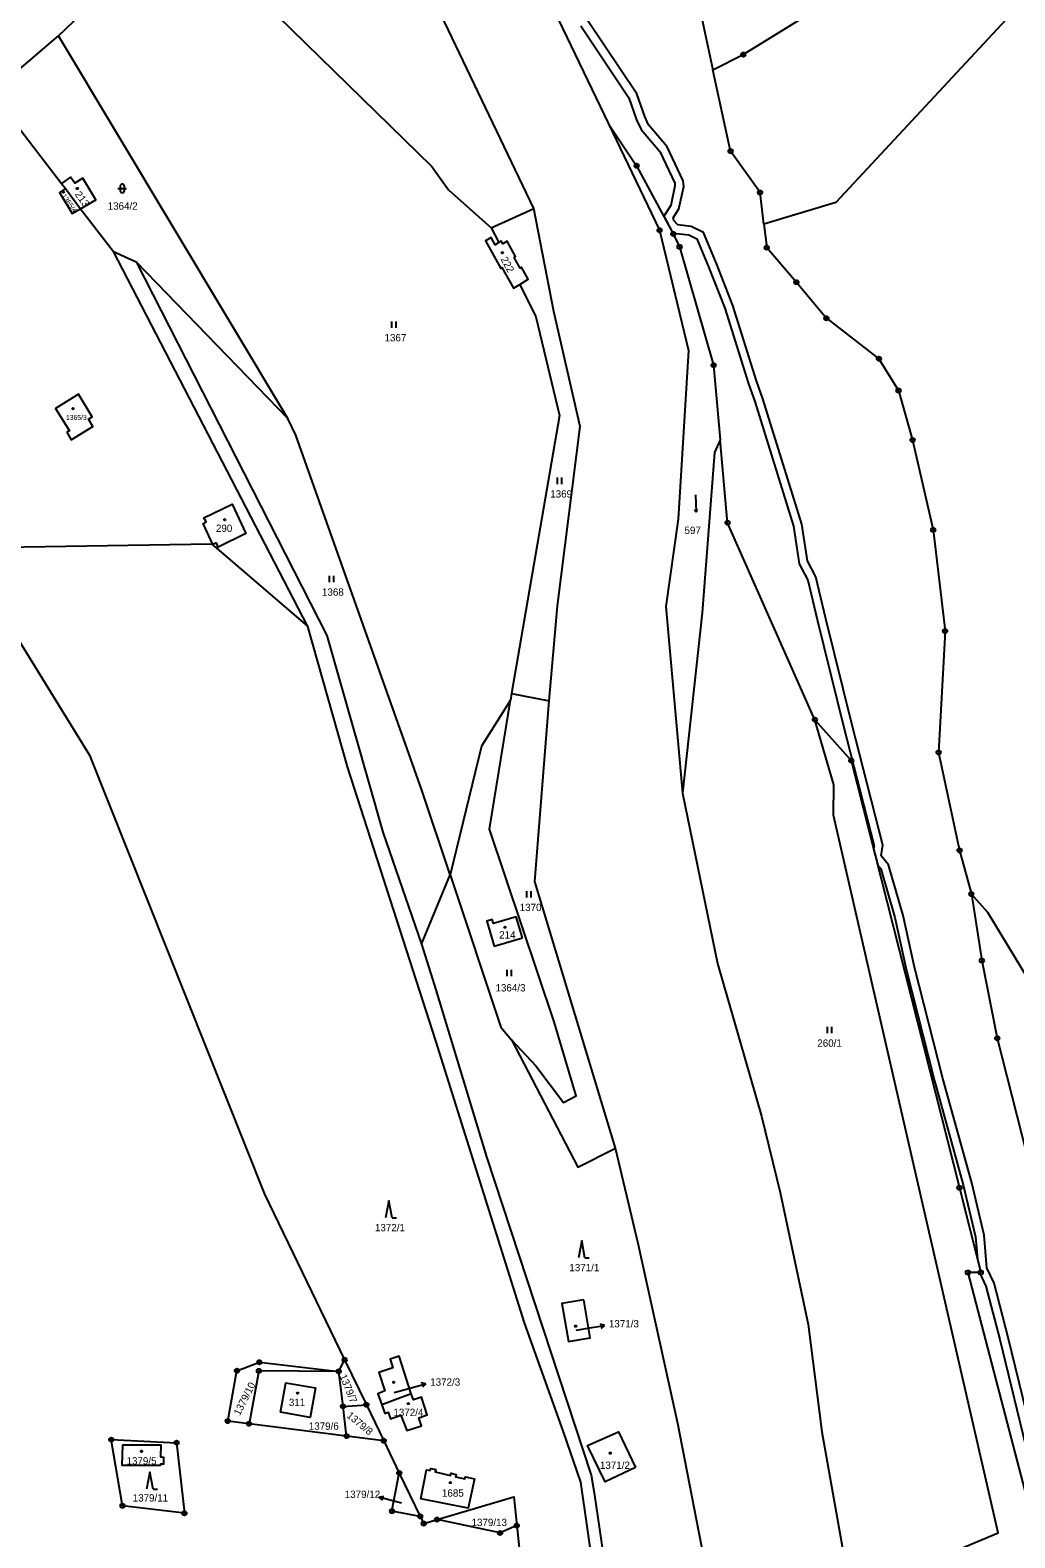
# Model space of a CAD drawing. Extents: x -680203 to -673936, y -1102717 to -1093650.
# Drawn here: x -675574.5 to -675346.1, y -1100750.7 to -1100400.9 of the extents above; entities that cross this region are included whole.
import ezdxf

# ---------------------------------------------------------------- set-up
doc = ezdxf.new("R2010")
doc.units = 0
for name, color, linetype in [('_Ideová část', 7, 'Continuous'), ('SOxx02xx_Koleje_param další_Popis10', 7, 'Continuous'), ('SOxx02xx_Staničení_Popis10', 7, 'Continuous'), ('SOxxxxxx_Koleje_hlavní_body_Popis10', 7, 'Continuous'), ('SOxxxxxx_Koleje_LN_parametry_Popis10', 7, 'Continuous'), ('SOxxxxxx_Koleje_param další_Popis10', 7, 'Continuous'), ('SOxxxxxx_Osa_bod_P', 7, 'Continuous'), ('x_prac', 7, 'Continuous')]:
    doc.layers.add(name, color=color, linetype=linetype)

msp = doc.modelspace()

# ---------------------------------------------------------------- linework, layer by layer
at = {"layer": '_Ideová část'}
msp.add_circle((-676417.7, -1099401.52), 1287.12, dxfattribs=at)
at = {"layer": 'SOxx02xx_Koleje_param další_Popis10'}
for centre, radius in [((-675409.1, -1100406.53), 0.5), ((-675409.1, -1100406.53), 0.0303), ((-675412.03, -1100428.94), 0.5), ((-675412.03, -1100428.94), 0.0303), ((-675433.83, -1100432.32), 0.5), ((-675433.83, -1100432.32), 0.0303), ((-675405.2, -1100438.53), 0.5), ((-675405.2, -1100438.53), 0.0303), ((-675428.52, -1100447.29), 0.5), ((-675428.52, -1100447.29), 0.5), ((-675428.52, -1100447.29), 0.0303), ((-675428.52, -1100447.29), 0.0303), ((-675425.33, -1100448.15), 0.5), ((-675425.33, -1100448.15), 0.0303), ((-675423.89, -1100451.14), 0.5), ((-675423.89, -1100451.14), 0.0303), ((-675403.66, -1100451.31), 0.5), ((-675403.66, -1100451.31), 0.0303), ((-675396.78, -1100459.34), 0.5), ((-675396.78, -1100459.34), 0.0303), ((-675389.82, -1100467.72), 0.5), ((-675389.82, -1100467.72), 0.0303), ((-675415.99, -1100478.63), 0.5), ((-675415.99, -1100478.63), 0.0303), ((-675377.65, -1100477.12), 0.5), ((-675377.65, -1100477.12), 0.0303), ((-675373.09, -1100484.48), 0.5), ((-675373.09, -1100484.48), 0.0303), ((-675369.84, -1100495.99), 0.5), ((-675369.84, -1100495.99), 0.0303), ((-675412.75, -1100515.16), 0.5), ((-675412.75, -1100515.16), 0.0303), ((-675365.05, -1100516.82), 0.5), ((-675365.05, -1100516.82), 0.0303), ((-675362.3, -1100540.29), 0.5), ((-675362.3, -1100540.29), 0.0303), ((-675392.49, -1100560.86), 0.5), ((-675392.49, -1100560.86), 0.0303), ((-675384.05, -1100570.35), 0.5), ((-675384.05, -1100570.35), 0.0303), ((-675363.8, -1100568.47), 0.5), ((-675363.8, -1100568.47), 0.0303), ((-675358.93, -1100591.19), 0.5), ((-675358.93, -1100591.19), 0.0303), ((-675356.2, -1100601.34), 0.5), ((-675356.2, -1100601.34), 0.0303), ((-675353.76, -1100616.75), 0.5), ((-675353.76, -1100616.75), 0.0303), ((-675350.19, -1100634.79), 0.5), ((-675350.19, -1100634.79), 0.0303), ((-675358.95, -1100669.47), 0.5), ((-675358.95, -1100669.47), 0.0303), ((-675357.01, -1100689.14), 0.5), ((-675357.01, -1100689.14), 0.0303), ((-675354, -1100689.14), 0.5), ((-675354, -1100689.14), 0.0303), ((-675521.35, -1100709.97), 0.5), ((-675521.35, -1100709.97), 0.0303), ((-675501.56, -1100709.41), 0.5), ((-675501.56, -1100709.41), 0.0303), ((-675526.54, -1100711.93), 0.5), ((-675526.54, -1100711.93), 0.0303), ((-675521.47, -1100711.97), 0.5), ((-675521.47, -1100711.97), 0.0303), ((-675502.94, -1100712.08), 0.5), ((-675502.94, -1100712.08), 0.0303), ((-675501.93, -1100720.2), 0.5), ((-675501.93, -1100720.2), 0.0303), ((-675496.53, -1100719.83), 0.5), ((-675496.53, -1100719.83), 0.0303), ((-675528.69, -1100723.61), 0.5), ((-675528.69, -1100723.61), 0.0303), ((-675523.73, -1100724.24), 0.5), ((-675523.73, -1100724.24), 0.0303), ((-675555.69, -1100727.93), 0.5), ((-675501.1, -1100727.11), 0.5), ((-675501.1, -1100727.11), 0.0303), ((-675492.5, -1100728.18), 0.5), ((-675555.69, -1100727.93), 0.0303), ((-675540.56, -1100728.63), 0.5), ((-675540.56, -1100728.63), 0.0303), ((-675492.5, -1100728.18), 0.0303), ((-675488.89, -1100735.67), 0.5), ((-675488.89, -1100735.67), 0.0303), ((-675553.09, -1100743.26), 0.5), ((-675553.09, -1100743.26), 0.0303), ((-675538.72, -1100745.02), 0.5), ((-675538.72, -1100745.02), 0.0303), ((-675490.58, -1100744.52), 0.5), ((-675490.58, -1100744.52), 0.0303), ((-675484.03, -1100745.74), 0.5), ((-675484.03, -1100745.74), 0.0303), ((-675483.23, -1100747.39), 0.5), ((-675483.23, -1100747.39), 0.0303), ((-675480.13, -1100746.47), 0.5), ((-675480.13, -1100746.47), 0.0303), ((-675461.64, -1100747.86), 0.5), ((-675461.64, -1100747.86), 0.0303), ((-675465.51, -1100749.59), 0.5), ((-675465.51, -1100749.59), 0.0303)]:
    msp.add_circle(centre, radius, dxfattribs=at)
at = {"layer": 'SOxx02xx_Staničení_Popis10'}
for p, q in [((-675447.83, -1100702.49), (-675444.22, -1100701.92)), ((-675444.22, -1100701.92), (-675441.26, -1100701.45)), ((-675441.26, -1100701.45), (-675442.32, -1100701.11)), ((-675441.26, -1100701.45), (-675442.17, -1100702.1)), ((-675490.1, -1100717), (-675485.6, -1100715.77)), ((-675485.6, -1100715.77), (-675482.7, -1100714.99)), ((-675482.7, -1100714.99), (-675483.8, -1100714.77)), ((-675482.7, -1100714.99), (-675483.54, -1100715.74)), ((-675493.61, -1100741.24), (-675492.51, -1100741.02)), ((-675490.71, -1100742.02), (-675493.61, -1100741.24)), ((-675493.61, -1100741.24), (-675492.77, -1100741.99)), ((-675488.37, -1100742.66), (-675490.71, -1100742.02))]:
    msp.add_line(p, q, dxfattribs=at)
at = {"layer": 'SOxxxxxx_Koleje_hlavní_body_Popis10'}
for p, q in [((-675553.66, -1100437.07), (-675553.66, -1100438.07)), ((-675552.66, -1100438.07), (-675552.66, -1100437.07)), ((-675554.16, -1100437.57), (-675552.16, -1100437.57)), ((-675490.65, -1100469.96), (-675490.65, -1100468.46)), ((-675489.65, -1100469.96), (-675489.65, -1100468.46)), ((-675452.18, -1100506.2), (-675452.18, -1100504.7)), ((-675451.18, -1100506.2), (-675451.18, -1100504.7)), ((-675420.15, -1100508.71), (-675420.01, -1100512.73)), ((-675420.01, -1100512.73), (-675420.36, -1100512.09)), ((-675420.01, -1100512.73), (-675419.69, -1100512.06)), ((-675505.1, -1100528.98), (-675505.1, -1100527.48)), ((-675504.1, -1100528.98), (-675504.1, -1100527.48)), ((-675459.28, -1100602.14), (-675459.28, -1100600.64)), ((-675458.28, -1100602.14), (-675458.28, -1100600.64)), ((-675463.89, -1100620.41), (-675463.89, -1100618.91)), ((-675462.89, -1100620.41), (-675462.89, -1100618.91)), ((-675389.53, -1100633.63), (-675389.53, -1100632.13)), ((-675388.53, -1100633.63), (-675388.53, -1100632.13)), ((-675491.3, -1100672.45), (-675492.05, -1100676.45)), ((-675490.55, -1100676.45), (-675491.3, -1100672.45)), ((-675490.55, -1100676.45), (-675489.55, -1100676.45)), ((-675446.58, -1100681.73), (-675447.33, -1100685.73)), ((-675445.83, -1100685.73), (-675446.58, -1100681.73)), ((-675445.83, -1100685.73), (-675444.83, -1100685.73)), ((-675546.76, -1100735.39), (-675547.51, -1100739.39)), ((-675546.01, -1100739.39), (-675546.76, -1100735.39)), ((-675546.01, -1100739.39), (-675545.01, -1100739.39))]:
    msp.add_line(p, q, dxfattribs=at)
for centre, start, end in [((-675553.16, -1100437.07), 0, 180), ((-675553.16, -1100438.07), 180, 359.9879)]:
    msp.add_arc(centre, 0.5, start, end, dxfattribs=at)
at = {"layer": 'SOxxxxxx_Koleje_LN_parametry_Popis10'}
for points in [[(-675338.41, -1100742.22), (-675347.67, -1100704.21), (-675350.94, -1100691.65), (-675352.62, -1100688.04), (-675353.25, -1100680.51), (-675356.12, -1100668.31), (-675362.81, -1100644.11), (-675369.4, -1100618.26), (-675372.03, -1100606.29), (-675375.38, -1100594.54), (-675377.08, -1100592.49), (-675376.73, -1100589.99), (-675383.92, -1100561.85), (-675389.94, -1100537.47), (-675392.27, -1100527.75), (-675394.22, -1100524.02), (-675395.51, -1100515.49), (-675404.55, -1100486.4), (-675406, -1100482.27), (-675411.53, -1100464.74), (-675415.32, -1100455.02), (-675418.3, -1100447.85), (-675421.17, -1100446.41), (-675424.28, -1100446.05), (-675425.19, -1100445.06), (-675425.39, -1100444.39), (-675424.04, -1100442.33), (-675422.92, -1100437.15), (-675423.03, -1100435.84), (-675426.78, -1100427.91), (-675431.06, -1100422.8), (-675431.97, -1100420.88), (-675433.81, -1100415.64), (-675445.17, -1100398.67)], [(-675446.75, -1100399.89), (-675435.61, -1100416.54), (-675433.83, -1100421.64), (-675432.76, -1100423.88), (-675428.48, -1100428.99), (-675424.99, -1100436.36), (-675424.94, -1100437.01), (-675425.92, -1100441.55), (-675427.54, -1100444.03), (-675425.69, -1100447.47), (-675425.26, -1100447.95), (-675421.75, -1100448.35), (-675419.86, -1100449.31), (-675417.18, -1100455.76), (-675413.41, -1100465.4), (-675407.9, -1100482.91), (-675406.45, -1100487.02), (-675397.47, -1100515.93), (-675396.14, -1100524.66), (-675394.15, -1100528.45), (-675391.88, -1100537.95), (-675385.86, -1100562.33), (-675378.77, -1100590.11), (-675378.87, -1100590.82), (-675377.9, -1100594.63), (-675377.18, -1100595.5), (-675373.97, -1100606.77), (-675371.34, -1100618.72)], [(-675371.34, -1100618.72), (-675364.75, -1100644.63), (-675358.06, -1100668.81), (-675355.23, -1100680.83), (-675354.8, -1100685.96), (-675354, -1100689.14), (-675354.31, -1100689.14), (-675352.84, -1100692.33), (-675349.61, -1100704.69), (-675340.31, -1100742.88), (-675338.51, -1100746.81), (-675336.16, -1100754.4)]]:
    msp.add_lwpolyline(points, dxfattribs=at)
at = {"layer": 'SOxxxxxx_Koleje_param další_Popis10'}
for centre in [(-675566.83, -1100438.41), (-675563.57, -1100437.6), (-675464.99, -1100452.48), (-675564.55, -1100488.71), (-675529.37, -1100514.44), (-675464.39, -1100609.02), (-675447.96, -1100701.59), (-675512.48, -1100717.13), (-675490.17, -1100714.63), (-675486.79, -1100719.55), (-675548.69, -1100730.63), (-675439.96, -1100731.06), (-675477.03, -1100737.88)]:
    msp.add_circle(centre, 0.175, dxfattribs=at)
at = {"layer": 'x_prac'}
for p, q in [((-675583.4, -1100415.37), (-675567.93, -1100402.18)), ((-675514.78, -1100490.95), (-675567.93, -1100402.18)), ((-675583.4, -1100415.37), (-675567.22, -1100436.42)), ((-675567.22, -1100436.42), (-675566.34, -1100437.63)), ((-675566.34, -1100437.63), (-675562.87, -1100442.31)), ((-675562.87, -1100442.31), (-675555.21, -1100452.21)), ((-675467.55, -1100446.7), (-675457.66, -1100442.21)), ((-675467.55, -1100446.7), (-675465.82, -1100450.16)), ((-675510.12, -1100539.25), (-675555.21, -1100452.21)), ((-675555.21, -1100452.21), (-675549.94, -1100454.63)), ((-675549.94, -1100454.63), (-675514.78, -1100490.95)), ((-675462.83, -1100554.78), (-675463.1, -1100556.34)), ((-675462.83, -1100554.78), (-675454.13, -1100556.51)), ((-675483.77, -1100612.97), (-675477.06, -1100596.84)), ((-675502.94, -1100712.08), (-675501.56, -1100709.41)), ((-675501.56, -1100709.41), (-675496.53, -1100719.83)), ((-675501.93, -1100720.2), (-675502.94, -1100712.08)), ((-675486.11, -1100717.28), (-675492.94, -1100719.85)), ((-675501.93, -1100720.2), (-675496.53, -1100719.83)), ((-675501.1, -1100727.11), (-675501.93, -1100720.2)), ((-675496.53, -1100719.83), (-675492.5, -1100728.18)), ((-675501.1, -1100727.11), (-675523.73, -1100724.24)), ((-675492.5, -1100728.18), (-675501.1, -1100727.11)), ((-675492.5, -1100728.18), (-675488.89, -1100735.67)), ((-675488.89, -1100735.67), (-675484.03, -1100745.74))]:
    msp.add_line(p, q, dxfattribs=at)
for points in [[(-675650.93, -1100184.82), (-675626.35, -1100211.55), (-675609.18, -1100237.88), (-675580.6, -1100270.38), (-675564.83, -1100288.77), (-675550.46, -1100304.47), (-675526.62, -1100326.56), (-675497.85, -1100353.88), (-675469.8, -1100376.57), (-675456.84, -1100388.22), (-675440.37, -1100422.57)], [(-675650.93, -1100184.82), (-675626.35, -1100211.55), (-675609.18, -1100237.88), (-675580.6, -1100270.38), (-675564.83, -1100288.77), (-675550.46, -1100304.47), (-675526.62, -1100326.56), (-675497.85, -1100353.88), (-675469.8, -1100376.57), (-675456.84, -1100388.22), (-675440.37, -1100422.57)], [(-675468.34, -1100328.8), (-675428.27, -1100382.16), (-675418.69, -1100398.14), (-675416.17, -1100410.06)], [(-675457.66, -1100442.21), (-675480.92, -1100393.48), (-675529.46, -1100368.65), (-675549.87, -1100353.94)], [(-675416.17, -1100410.06), (-675409.1, -1100406.53), (-675390.06, -1100394.75), (-675375.33, -1100373.31), (-675349.64, -1100356.38)], [(-675567.93, -1100402.18), (-675539.87, -1100375.27), (-675481.31, -1100432.51), (-675477.48, -1100437.95), (-675467.55, -1100446.7)], [(-675318.76, -1100393.56), (-675344.06, -1100393.95), (-675387.64, -1100440.89), (-675404.37, -1100445.88)], [(-675404.37, -1100445.88), (-675405.2, -1100438.53), (-675412.03, -1100428.94), (-675416.17, -1100410.06)], [(-675440.37, -1100422.57), (-675433.83, -1100432.32), (-675425.33, -1100448.15), (-675423.89, -1100451.14), (-675415.99, -1100478.63), (-675414.45, -1100495.89)], [(-675440.37, -1100422.57), (-675428.52, -1100447.29), (-675421.84, -1100475.21), (-675424.17, -1100514.37), (-675427.03, -1100534.61), (-675423.16, -1100577.9)], [(-675440.37, -1100422.57), (-675428.52, -1100447.29), (-675421.84, -1100475.21), (-675424.17, -1100514.37), (-675427.03, -1100534.61), (-675423.16, -1100577.9)], [(-675562.87, -1100442.31), (-675559.24, -1100440.26), (-675562.27, -1100435.18), (-675564.17, -1100436.34), (-675565.17, -1100434.96), (-675567.22, -1100436.42)], [(-675566.34, -1100437.63), (-675567.72, -1100438.54), (-675564.75, -1100443.39), (-675562.87, -1100442.31)], [(-675454.13, -1100556.51), (-675452.16, -1100534.47), (-675446.94, -1100492.85), (-675453.04, -1100466.15), (-675457.66, -1100442.21)], [(-675404.37, -1100445.88), (-675403.66, -1100451.31), (-675396.78, -1100459.34), (-675389.82, -1100467.72), (-675377.65, -1100477.12), (-675373.09, -1100484.48), (-675369.84, -1100495.99), (-675365.05, -1100516.82), (-675362.3, -1100540.29), (-675363.8, -1100568.47), (-675358.93, -1100591.19), (-675356.2, -1100601.34)], [(-675465.82, -1100450.16), (-675466.66, -1100450.66), (-675467.61, -1100448.98), (-675468.93, -1100449.78), (-675465.36, -1100456.13), (-675465.09, -1100455.97), (-675462.43, -1100460.74), (-675460.95, -1100459.86)], [(-675460.95, -1100459.86), (-675458.96, -1100458.67), (-675460.53, -1100455.88), (-675460.87, -1100456.09), (-675462.23, -1100453.61), (-675461.9, -1100453.42), (-675463.86, -1100449.85), (-675464.89, -1100450.46), (-675465.25, -1100449.82), (-675465.82, -1100450.16)], [(-675549.94, -1100454.63), (-675505.66, -1100541.35), (-675492.68, -1100586.98), (-675483.77, -1100612.97)], [(-675460.95, -1100459.86), (-675457.18, -1100467.37), (-675451.75, -1100490.25), (-675462.83, -1100554.78)], [(-675566.01, -1100494.18), (-675564.96, -1100495.89), (-675559.96, -1100492.82), (-675561, -1100491.12), (-675560.1, -1100490.6), (-675563.32, -1100485.35), (-675568.61, -1100488.63), (-675565.42, -1100493.82), (-675566.01, -1100494.18)], [(-675477.06, -1100596.84), (-675483.66, -1100577.25), (-675512.88, -1100494.85), (-675514.78, -1100490.95)], [(-675414.45, -1100495.89), (-675415.8, -1100498.88), (-675418.66, -1100536.04), (-675423.16, -1100577.9)], [(-675392.49, -1100560.86), (-675412.75, -1100515.16), (-675414.45, -1100495.89)], [(-675531.32, -1100519.86), (-675532.13, -1100520.2), (-675534.41, -1100515.33), (-675533.69, -1100514.95), (-675534.19, -1100514), (-675527.67, -1100510.86), (-675524.48, -1100517.69), (-675530.87, -1100520.82), (-675531.32, -1100519.86)], [(-675590.47, -1100521.02), (-675532.43, -1100520.07), (-675510.12, -1100539.25)], [(-675590.47, -1100521.02), (-675560.75, -1100569.07), (-675520.12, -1100670.93), (-675501.56, -1100709.41)], [(-675378.05, -1101046.98), (-675407.14, -1100948.73), (-675417.31, -1100897.18), (-675423.43, -1100866.39), (-675434.86, -1100820.57), (-675446.8, -1100737.82), (-675450.82, -1100726.11), (-675459.86, -1100700.86), (-675480.45, -1100635.37), (-675500.79, -1100572.05), (-675510.12, -1100539.25)], [(-675463.1, -1100556.34), (-675469.85, -1100567.04), (-675477.06, -1100596.84)], [(-675462.86, -1100635.15), (-675457.22, -1100641.16), (-675450.8, -1100649.72), (-675447.88, -1100648.17), (-675452.96, -1100630.97), (-675467.98, -1100586.3), (-675463.1, -1100556.34)], [(-675438.77, -1100660.27), (-675457.45, -1100598.45), (-675454.13, -1100556.51)], [(-675370.8, -1100758.27), (-675349.99, -1100749.57), (-675388.18, -1100582.99), (-675388.1, -1100575.99), (-675392.49, -1100560.86)], [(-675392.49, -1100560.86), (-675384.05, -1100570.35), (-675358.95, -1100669.47), (-675354, -1100689.14), (-675357.01, -1100689.14), (-675338.32, -1100760.84), (-675340.97, -1100761.62)], [(-675423.16, -1100577.9), (-675415.1, -1100617.43), (-675404.89, -1100652.85), (-675400.52, -1100670.61), (-675394.03, -1100701.22), (-675390.87, -1100726.12), (-675384.67, -1100760.89)], [(-675423.16, -1100577.9), (-675415.1, -1100617.43), (-675404.89, -1100652.85), (-675400.52, -1100670.61), (-675394.03, -1100701.22), (-675390.87, -1100726.12), (-675384.67, -1100760.89)], [(-675477.06, -1100596.84), (-675465.31, -1100632.24), (-675462.86, -1100635.15)], [(-675356.2, -1100601.34), (-675353.76, -1100616.75), (-675350.19, -1100634.79), (-675337.79, -1100683.72), (-675333.58, -1100693.19), (-675315.67, -1100760.91), (-675312.34, -1100760.18), (-675310.41, -1100766.09), (-675313.89, -1100767.13), (-675308, -1100794.02), (-675303.22, -1100813.03), (-675293.67, -1100842.42), (-675289.8, -1100856.17), (-675287.11, -1100864.73)], [(-675339.98, -1100626.04), (-675352.36, -1100605.6), (-675356.2, -1100601.34)], [(-675460.33, -1100611.48), (-675461.78, -1100606.62), (-675467.03, -1100608.18), (-675467.33, -1100607.2), (-675468.59, -1100607.58), (-675466.89, -1100613.41), (-675460.33, -1100611.48)], [(-675483.77, -1100612.97), (-675480.43, -1100623.52), (-675468.68, -1100662.28), (-675444.36, -1100736.16), (-675443.7, -1100740.24), (-675431.63, -1100822.49), (-675416.24, -1100884.61), (-675405.81, -1100937.77)], [(-675462.86, -1100635.15), (-675447.48, -1100664.73), (-675438.77, -1100660.27)], [(-675397.77, -1100862.96), (-675408.9, -1100803.32), (-675424.25, -1100724.19), (-675433.49, -1100682.43), (-675438.77, -1100660.27)], [(-675446.12, -1100695.49), (-675451.18, -1100696.36), (-675449.64, -1100705.17), (-675444.61, -1100704.3), (-675446.12, -1100695.49)], [(-675523.73, -1100724.24), (-675528.69, -1100723.61), (-675526.54, -1100711.93), (-675521.35, -1100709.97), (-675502.94, -1100712.08)], [(-675486.11, -1100717.28), (-675488.91, -1100708.58), (-675491.02, -1100709.27), (-675490.37, -1100711.24), (-675493.64, -1100712.36), (-675492.22, -1100716.63), (-675493.84, -1100717.28), (-675492.94, -1100719.85)], [(-675502.94, -1100712.08), (-675521.47, -1100711.97), (-675523.73, -1100724.24)], [(-675516.48, -1100721.56), (-675515.23, -1100714.78), (-675508.32, -1100715.89), (-675509.59, -1100722.81), (-675516.48, -1100721.56)], [(-675492.94, -1100719.85), (-675492.24, -1100721.84), (-675491.49, -1100721.56), (-675490.93, -1100723.12), (-675488.56, -1100722.22), (-675487.11, -1100725.81), (-675483.75, -1100724.72), (-675484.37, -1100722.84), (-675482.41, -1100722.15), (-675483.7, -1100718.05), (-675485.6, -1100718.68), (-675486.11, -1100717.28)], [(-675434.1, -1100734.39), (-675441.17, -1100737.7), (-675445.25, -1100729.31), (-675438.06, -1100726.1), (-675434.1, -1100734.39)], [(-675540.56, -1100728.63), (-675538.72, -1100745.02), (-675553.09, -1100743.26), (-675555.69, -1100727.93), (-675540.56, -1100728.63)], [(-675544.24, -1100733.93), (-675553.14, -1100733.89), (-675553.03, -1100729.14), (-675544.22, -1100729.16), (-675544.24, -1100731.95), (-675543.55, -1100731.96), (-675543.57, -1100733.64), (-675544.27, -1100733.6), (-675544.24, -1100733.93)], [(-675481.73, -1100735.12), (-675481.6, -1100734.6), (-675480.44, -1100734.88), (-675480.57, -1100735.4), (-675477.03, -1100736.25), (-675476.89, -1100735.73), (-675475.73, -1100736.01), (-675475.87, -1100736.53), (-675473.66, -1100737.05), (-675473.53, -1100736.52), (-675471.46, -1100737.03), (-675472.89, -1100743.83), (-675483.89, -1100741.66), (-675482.6, -1100734.91), (-675481.73, -1100735.12)], [(-675484.03, -1100745.74), (-675490.58, -1100744.52), (-675488.89, -1100735.67)], [(-675480.13, -1100746.47), (-675462.34, -1100741.18), (-675461.64, -1100747.86)], [(-675484.03, -1100745.74), (-675483.23, -1100747.39), (-675480.13, -1100746.47)], [(-675461.64, -1100747.86), (-675465.51, -1100749.59), (-675480.13, -1100746.47)], [(-675461.64, -1100747.86), (-675453.58, -1100824.76), (-675455.91, -1100853.94), (-675450.31, -1100906.18)]]:
    msp.add_lwpolyline(points, dxfattribs=at)

# ---------------------------------------------------------------- texts
at = {"layer": 'SOxxxxxx_Osa_bod_P'}
for s, height, rotation, p in [('1365/4', 1.14, 305, (-675567.24, -1100439.34)), ('213', 1.7, 305, (-675564.22, -1100438.96)), ('222', 1.7, 299, (-675465.44, -1100454.01)), ('1379/7', 1.7, 292, (-675502.77, -1100713.15)), ('1379/10', 1.7, 63, (-675525.9, -1100722.48)), ('1379/8', 1.7, 320, (-675501.22, -1100722.57))]:
    msp.add_text(s, height=height, rotation=rotation, dxfattribs=at).set_placement(p)
for s, height, p in [('1364/2', 1.7, (-675556.53, -1100442.51)), ('1367', 1.7, (-675492.31, -1100473.08)), ('1365/3', 1.14, (-675566.2, -1100491.3)), ('1369', 1.7, (-675453.87, -1100509.32)), ('290', 1.7, (-675531.42, -1100517.29)), ('597', 1.7, (-675422.73, -1100517.77)), ('1368', 1.7, (-675506.82, -1100532.1)), ('1370', 1.7, (-675460.96, -1100605.27)), ('214', 1.7, (-675465.73, -1100611.65)), ('1364/3', 1.7, (-675466.57, -1100623.93)), ('260/1', 1.7, (-675391.93, -1100636.76)), ('1372/1', 1.7, (-675494.53, -1100679.57)), ('1371/1', 1.7, (-675449.44, -1100688.85)), ('1371/3', 1.7, (-675440.26, -1100701.88)), ('1372/3', 1.7, (-675481.71, -1100715.41)), ('311', 1.7, (-675514.5, -1100720.12)), ('1372/4', 1.7, (-675490.25, -1100722.44)), ('1379/6', 1.7, (-675509.88, -1100725.64)), ('1379/5', 1.7, (-675552.15, -1100733.7)), ('1371/2', 1.7, (-675442.35, -1100734.72)), ('1379/11', 1.7, (-675550.72, -1100742.29)), ('1379/12', 1.7, (-675501.54, -1100741.46)), ('1685', 1.7, (-675478.99, -1100741.17)), ('1379/13', 1.7, (-675472.13, -1100747.98))]:
    msp.add_text(s, height=height, dxfattribs=at).set_placement(p)

doc.saveas('drawing.dxf')
